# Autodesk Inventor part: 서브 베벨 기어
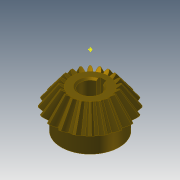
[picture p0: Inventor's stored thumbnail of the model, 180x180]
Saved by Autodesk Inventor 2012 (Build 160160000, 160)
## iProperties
Created: 2014-10
Part Number: 서브 베벨 기어
Material: Steel, Mild
Document SubType Name: Modeling
Designer: KYOUNG IL JANG
Categories: <?xml version="1.0" encoding="UTF-16"?> <MemberInstance><Categories><FamilyTemplate><FamilyTemplateParameter ValueType="xs:double" Id="1" ObjectReferenceKey="da
Mass: 134.866 g
Surface Area: 63.6518 cm^2
Volume: 17.1585 cm^3
Density: 7.86 g/cm^3
CustomPartVersion: 1
Company: 한국ATC센터
Author: KYOUNG IL JANG
Revision Number: 1
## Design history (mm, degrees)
node "맨 위 점"
node "메쉬 평면2"
sketch "톱니 본체 스케치"
  geometry: L1 (0, 0)-(18.003, -31.331); L2 (18.003, -31.331)-(21.664, -28.891); L3 (21.664, -28.891)-(0, 0); L4 (20, -30)-(0, 0); L5 (10.813, -18.818)-(13.012, -17.352); L6 (18.003, -31.331)-(10.813, -18.818); L7 (21.664, -28.891)-(13.012, -17.352); L8 (0, -39.387)-(0, 6.564) reference; L9 (0, -30)-(21.664, -30)
  constraints: 16 end point, 4 point on line, 3 perpendicular, 2 collinear, 1 horizontal alignment, 1 vertical alignment
  dimensions: "d0" = 40 diameter of L4.start L8 (= da_de); "d1" = 36.00616 diameter of L1.end L8 (= da_dfe); "d2" = 43.3282 diameter of L2.end L8 (= da_dae); "d3" = 14.4 distance between parallel lines of L2 L5 (= da_b); "d4" = 28.8906 vertical distance of L2.end L1.start (= da_ve)
revolve "톱니 본체" sketch "톱니 본체 스케치" stored, may be unused: angle "d5" = 90 deg
node "시작점"
node "톱니 평면"
sketch "시작 스케치"
  geometry: L1 (0, -23.505)-(0, 10.645) reference; L2 (-0.834, -2.928)-(0.834, -2.928); A1 r 8.898 centre (-9.698, -3.713) between (-0.834, -2.928) and (-3.903, 3.04); A2 r 8.898 centre (9.698, -3.713) between (3.903, 3.04) and (0.834, -2.928); A3 r 27.357 centre (0, -24.037) between (3.903, 3.04) and (-3.903, 3.04); 1 further point
  constraints: 6 point on circle, 3 centre point, 3 symmetric about line, 2 end point, 1 coincident, 1 perpendicular, 1 other
  dimensions: "d7" = 8.89846 radius of A1 (= fd_rr); "d8" = 9.69794 horizontal distance of point (0, -24.037) A1.centre (= fd_x); "d9" = 20.32439 vertical distance of point (0, -24.037) A1.centre (= fd_y); "d57" = 27.35701 radius of A3 (= 0.5 x fd_dva + 0.3 x da_he); "d58" = 21.10901 distance from line of A3.centre L2 (= 0.5 x fd_dva - 1.12 x da_he)
node "끝점"
  node "끝 평면"
sketch "3D 스케치 오른쪽"
  node "Helical Curve Right" dims "d65" = 229.90621 (computed from da_dm, da_delta, da_beta), "d66" = 31.5, "d67" = 40 (= da_de), "d68" = -5.88003 (= -da_delta), "d69" = 12.16458 (computed from fd_loft, da_delta)
node "끝 평면 오른쪽"
sketch "끝 스케치 오른쪽"
  geometry: L1 (0, -22.649)-(0, 12.15) reference; L2 (-0.497, -1.72)-(0.497, -1.72); A1 r 5.299 centre (-5.775, -2.187) between (-0.497, -1.72) and (-2.324, 1.834); A2 r 5.299 centre (5.775, -2.187) between (2.324, 1.834) and (0.497, -1.72); A3 r 16.291 centre (0, -14.29) between (2.324, 1.834) and (-2.324, 1.834); 1 further point
  constraints: 6 point on circle, 3 centre point, 3 symmetric about line, 2 end point, 1 coincident, 1 perpendicular, 1 other
  dimensions: "d70" = 5.77526 horizontal distance of A3.centre A1.centre (computed from fd_x, fd_ratio); "d71" = 12.10346 vertical distance of point (0, -14.29) A1.centre (computed from fd_y, fd_ratio); "d72" = 5.29916 radius of A1 (computed from fd_rr, fd_ratio); "d73" = 12.57071 distance from line of point (0, -14.29) L2 (computed from d58, fd_ratio); "d74" = 16.29149 radius of A3 (computed from d57, fd_ratio)
feature "로프트 오른쪽" sketch "끝 스케치 오른쪽" dims "d75" = 0, "d77" = 0, "d79" = 0, "d80" = 90 deg, "d85" = 20, "d92" = 90 deg, "d93" = 90 deg, "da_teethtype" = 0 [user parameter]
sketch "3D 스케치 왼쪽"
  node "Helical Curve Left" dims "d26" = 229.90621 (computed from da_dm, da_delta, da_beta), "d27" = 12.16458 (computed from fd_loft, da_delta), "d28" = 40 (= da_de), "d29" = -5.88003 (= -da_delta)
node "끝 평면 왼쪽"
sketch "끝 스케치 왼쪽" dims "d56" = 10.82768 (derived)
  geometry: L1 (0, -35.087)-(0, 18.089) reference; L2 (-0.497, -1.716)-(0.497, -1.716); A1 r 5.299 centre (-5.775, -2.183) between (-0.497, -1.716) and (-2.324, 1.838); A2 r 5.299 centre (5.775, -2.183) between (2.324, 1.838) and (0.497, -1.716); A3 r 16.291 centre (0, -14.287) between (2.324, 1.838) and (-2.324, 1.838); 2 further points; 1 other entity
  constraints: 6 point on circle, 3 centre point, 3 symmetric about line, 2 end point, 1 coincident, 2 other
  dimensions: "d30" = 5.29916 radius of A1 (computed from fd_rr, fd_ratio); "d31" = 5.77526 horizontal distance of point (0, -14.287) A1.centre (computed from fd_x, fd_ratio); "d32" = 12.10346 vertical distance of A1.centre point (0, -14.287) (computed from fd_y, fd_ratio); "d61" = 16.29149 radius of A3 (computed from d57, fd_ratio); "d62" = 12.57071 distance from line of point (0, -14.287) L2 (computed from d58, fd_ratio)
feature "로프트 왼쪽" sketch "끝 스케치 왼쪽" dims "d35" = 0, "d37" = 0, "d39" = 0, "d40" = 90 deg, "d84" = 10, "d90" = 90 deg, "d91" = 90 deg, "da_teethtype" = 0 [user parameter]
sketch "본체 스케치"
  geometry: L1 (0, -35.038)-(0, -19.531) reference; L2 (18.003, -31.331)-(10.813, -18.818) reference; L3 (10.813, -18.818)-(0, -18.818); L4 (18.003, -31.331)-(0, -31.331)
  constraints: 4 end point, 2 perpendicular, 2 point on line
revolve "본체 고정" sketch "본체 스케치" stored, may be unused: angle "d46" = 90 deg
sketch "Sketch6"
  geometry: L1 (20, -30)-(0, 0) reference; L2 (0, -37.8)-(0, 6.3) reference
feature "피치 지름" sketch "Sketch6" dims angle "d47" = 90 deg
sketch "스케치8"
  geometry: C1 r 17 at (0, 0); 1 further point
  constraints: 1 centre point, 1 coincident
  dimensions: "d94" = 34 diameter of C1
extrude "돌출1" join sketch "스케치8" distance "d95" = 10; taper "d96" = 0 deg
sketch "스케치9"
  geometry: 1 further point
hole "구멍1" sketch "스케치9" at (0, 0) diameter "d97" = 12; stored, may be unused: countersink angle "d101" = 90 deg, drill point angle "d103" = 118 deg; dims "d98" = 6, "d99" = 4, "d100" = 2, "d102" = 8
sketch "스케치10"
  geometry: 1 further point
sketch "스케치11"
  geometry: 1 further point
sketch "스케치12"
  geometry: L1 (-2, 5.657)-(-2, 7.8); L2 (-2, 7.8)-(2, 7.8); L3 (2, 7.8)-(2, 5.657); A1 r 6 centre (0, 0) between (-2, 5.657) and (2, 5.657) reference; 1 further point
  constraints: 6 end point, 2 parallel, 2 point on circle, 1 perpendicular, 1 vertical
  dimensions: "d104" = 4 distance of L1.end L2.end; "d105" = 13.8 dimension on A1 L2
extrude "돌출2" cut sketch "스케치12" stored distance "d106" = 7; taper "d107" = 0 deg
chamfer "모따기1" distance "d108" = 1; stored, may be unused: second distance "d109" = 2, angle "d110" = 45 deg
body "Solid1"
feature "로프트" dims "d17" = 0, "d18" = 90 deg, "d19" = 0, "d20" = 90 deg, "d89" = 0, "da_teethtype" = 0 [user parameter]
pattern_circular "원형 패턴" dims angle "d22" = 360 deg, "d88" = 0, "da_teethtype" = 0 [user parameter]
pattern_circular "원형 패턴 오른쪽" dims angle "d82" = 360 deg, "da_teethtype" = 0 [user parameter]
pattern_circular "원형 패턴 왼쪽" dims angle "d42" = 360 deg, "da_teethtype" = 0 [user parameter]
sketch "끝 스케치"
  geometry: L1 (0, -15.359)-(0, 6.983) reference; L2 (-0.497, -1.72)-(0.497, -1.72); A1 r 5.299 centre (-5.775, -2.187) between (-0.497, -1.72) and (-2.324, 1.834); A2 r 5.299 centre (5.775, -2.187) between (2.324, 1.834) and (0.497, -1.72); A3 r 16.291 centre (0, -14.29) between (2.324, 1.834) and (-2.324, 1.834); 1 further point
  constraints: 6 point on circle, 3 centre point, 3 symmetric about line, 2 end point, 1 coincident, 1 other
  dimensions: "d12" = 5.29916 radius of A1 (computed from fd_rr, fd_ratio); "d15" = 5.77526 horizontal distance of A1.centre point (0, -14.29) (computed from fd_x, fd_ratio); "d16" = 12.10346 vertical distance of A1.centre point (0, -14.29) (computed from fd_y, fd_ratio); "d59" = 16.29149 radius of A3 (computed from d57, fd_ratio); "d60" = 12.57071 distance from line of A3.centre L2 (computed from d58, fd_ratio)
body "Srf1"
other parameters: "da_b" = 14.4 [user parameter; used in 2 equation terms], "da_de" = 40 [user parameter; used in 4 equation terms], "da_dae" = 43.3282 [user parameter; used in 2 equation terms], "da_dfe" = 36.00616 [user parameter; used in 1 equation term], "da_le" = 36.05551 [user parameter; used in 1 equation term], "da_omega" = 90 deg [user parameter; used in 1 equation term], "da_beta" = 0 [user parameter; used in 2 equation terms], "da_delta" = 5.88003 [user parameter; used in 8 equation terms], "da_alpha" = 20 deg [user parameter; used in 2 equation terms], "da_he" = 4.4 [user parameter; used in 4 equation terms], "da_ve" = 28.8906 [user parameter; used in 1 equation term], "fd_dv" = 48.07402 (computed from da_de, da_delta) [user parameter; used in 1 equation term], "fd_dva" = 52.07402 (computed from da_dae, da_delta) [user parameter; used in 3 equation terms], "fd_dvb" = 45.1748 (computed from fd_dv, da_alpha) [user parameter; used in 2 equation terms], "da_zv" = 240.37008 [user parameter; used in 1 equation term], "fd_loft" = 14.62 (= da_b + 0.05 x da_he) [user parameter; used in 4 equation terms], "fd_ratio" = 5.95514 (computed from da_le, fd_loft) [user parameter; used in 15 equation terms], "fd_rr" = 8.89846 (computed from fd_dd, fd_dvb) [user parameter; used in 6 equation terms], "fd_angle" = 0.66075 (computed from da_zv) [user parameter; used in 4 equation terms], "fd_x1" = 1.58709 (computed from da_dvw, fd_angle) [user parameter; used in 1 equation term], "fd_y1" = 23.98456 (computed from da_dvw, fd_angle) [user parameter; used in 1 equation term], "fd_x2" = 8.11084 (computed from fd_rr, fd_angle2, fd_angle) [user parameter; used in 1 equation term], "fd_y2" = 3.66016 (computed from fd_rr, fd_angle2, fd_angle) [user parameter; used in 1 equation term], "fd_x" = 9.69794 (= fd_x1 + fd_x2) [user parameter; used in 4 equation terms], "fd_y" = 20.32439 (= fd_y1 - fd_y2) [user parameter; used in 4 equation terms], "fd_angle2" = 3.57832 (computed from fd_dvb, fd_dd, da_alpha) [user parameter; used in 2 equation terms], "fd_dd" = 48.55402 (= fd_dva - 0.8 x da_he) [user parameter; used in 2 equation terms], "da_dvw" = 48.07402 [user parameter; used in 2 equation terms], "d11" = 14.62 (= fd_loft), "da_dm" = 32.01232 [user parameter; used in 2 equation terms], "da_x" = 0 [user parameter], "da_m" = 2 [user parameter], "d48" = 0, "d49" = 0, "d50" = 90 deg (= da_omega), "d51" = 9 deg (computed from da_z), "d52" = 0, "d53" = 0, "d54" = 0
